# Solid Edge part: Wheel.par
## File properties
Title: Wheel
Author: windows
Template: Iso Metric Part.par
Last saved by: windows
Revision: 4
Application: Solid Edge
Username: windows
Density: 886,000 kg/m^3
Accuracy: 0,990
Material: Polyethylene, low density
Face Style: Blue
Fill Style: ANSI34(Plastic)
Virtual Style: ANSI34(Plastic)
Grouping: Non-metals\Plastics
LibraryName: Materials
Coef. of Thermal Exp: 0.00016
Thermal Conductivity: 3.9
Specific Heat: 2219.0
Modulus of Elasticity: 144789897.0
Poisson's Ratio: 0.35
Yield Stress: 9652659.8
Ultimate Stress: 0.0
Elongation: 0.0
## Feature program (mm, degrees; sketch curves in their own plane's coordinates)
sketch for "unnamed Protrusion 1" #1 plane through (0, 0, 0) normal (0, -1, 0) x-axis (1, 0, 0)
  circle centre (0, 0) radius 30
sketch for "unnamed Protrusion 1" #2 plane through (0, 0, 0) normal (0, -1, 0) x-axis (1, 0, 0)
  circle centre (0, 0) radius 2.5
extrude "unnamed Protrusion 1" add finite 12 along +normal
sketch for "Cutout_1" plane through (0, -12, 0) normal (0, -1, 0) x-axis (1, 0, 0)
  line (-7, 29.1719) -> (-2.3781, 9.9107)
  line (-2.3781, 9.9107) -> (2.3781, 9.9107)
  line (7, 29.1719) -> (2.3781, 9.9107)
  arc centre (0, 0) radius 30 from (-7, 29.1719) to (7, 29.1719) cw
extrude "Cutout_1" cut finite 139.9702 symmetric
pattern "unnamed Pattern 1" of "Cutout_1"
pattern "unnamed Pattern 2"
fillet "Round_1" radius 1
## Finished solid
Body 1: solid body, 75 faces, 218 edges, 144 vertices.
  Faces by surface: plane 38, cylinder 37
  Edges by curve: line 144, ellipse 48, circle 26
Bounding box of the edges (mm): 58.344 x 12.000 x 58.344, from (-29.1719, -12, -29.1719) to (29.1719, 0, 29.1719).
Cylindrical faces by radius (mm): R1 x24, R2.5 x1, R30 x12
Planar faces by outward normal: +x 1, +y 1, +z 1, -x 1, -y 1, -z 1, oblique 32
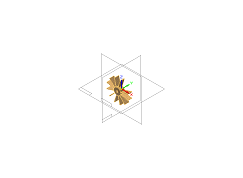
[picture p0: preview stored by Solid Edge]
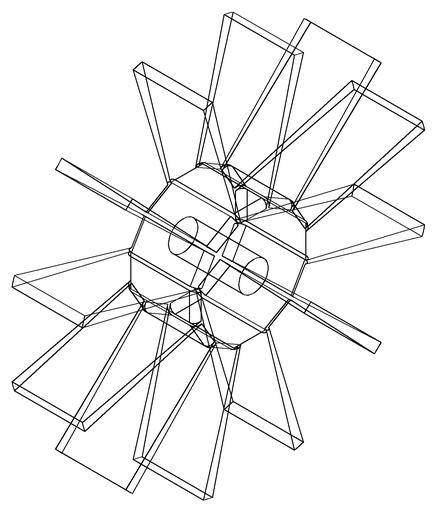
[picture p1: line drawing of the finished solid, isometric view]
